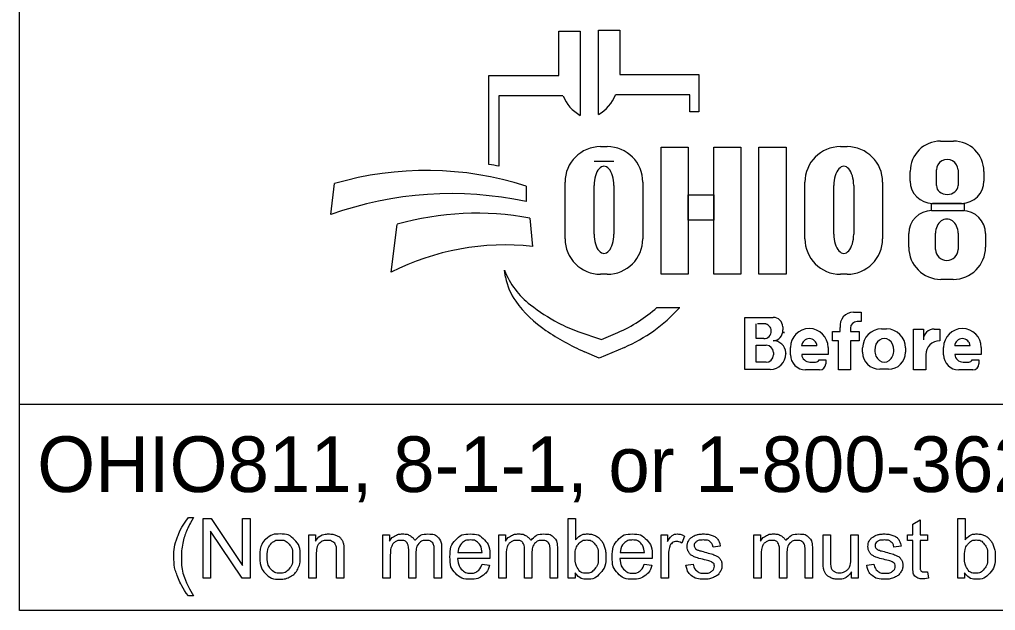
# Model space of a CAD drawing. Extents: x 0 to 34, y -32.5 to 22.
# Drawn here: x 2.378 to 4.831, y 2.305 to 3.791 of the extents above; entities that cross this region are included whole.
import ezdxf

# ---------------------------------------------------------------- set-up
doc = ezdxf.new("R2010")
doc.units = 0
doc.layers.add('GM_X_Adjacent_County', color=7, linetype='Continuous')
doc.layers.add('GM_X_Township', color=7, linetype='Continuous')

msp = doc.modelspace()

# ---------------------------------------------------------------- linework, layer by layer
at = {"layer": 'GM_X_Adjacent_County'}
for p, q in [((3.7335, 3.6502), (3.7335, 3.7617)), ((3.7335, 3.7617), (3.7872, 3.7617)), ((3.7872, 3.7617), (3.7872, 3.5496)), ((3.8329, 3.5519), (3.8329, 3.764)), ((3.8329, 3.764), (3.8865, 3.764)), ((3.8865, 3.764), (3.8865, 3.6525)), ((3.5576, 3.4263), (3.5576, 3.6502)), ((3.5576, 3.6502), (3.7335, 3.6502)), ((3.8865, 3.6525), (4.0857, 3.6525)), ((4.0857, 3.6525), (4.0857, 3.5587)), ((3.5828, 3.5987), (3.5828, 3.4219)), ((3.7439, 3.5987), (3.5828, 3.5987)), ((4.0625, 3.6011), (3.8761, 3.6011)), ((4.0625, 3.5587), (4.0625, 3.6011)), ((4.0857, 3.5587), (4.0625, 3.5587)), ((4.6931, 3.485), (4.7258, 3.485)), ((3.8385, 3.471), (3.8551, 3.471)), ((4.4416, 3.471), (4.4581, 3.471)), ((3.8718, 3.434), (3.822, 3.434)), ((4.683, 3.373), (4.683, 3.4123)), ((4.7371, 3.4123), (4.7371, 3.373)), ((4.6168, 3.3844), (4.6168, 3.4087)), ((4.8022, 3.4087), (4.8022, 3.3844)), ((3.1602, 3.3), (3.1696, 3.3781)), ((3.6509, 3.3716), (3.6509, 3.3328)), ((3.7491, 3.2395), (3.7491, 3.3815)), ((3.822, 3.2509), (3.822, 3.3732)), ((3.8718, 3.3732), (3.8718, 3.2509)), ((3.9445, 3.3815), (3.9445, 3.2395)), ((4.3521, 3.2395), (4.3521, 3.3815)), ((4.425, 3.2509), (4.425, 3.3732)), ((4.4748, 3.3732), (4.4748, 3.2509)), ((4.5476, 3.3815), (4.5476, 3.2395)), ((4.7462, 3.3284), (4.6728, 3.3284)), ((3.6608, 3.291), (3.6671, 3.2201)), ((4.671, 3.3101), (4.7483, 3.3101)), ((3.312, 3.1555), (3.3267, 3.2756)), ((4.6131, 3.2182), (4.6131, 3.2522)), ((4.6806, 3.2122), (4.6806, 3.2531)), ((4.7374, 3.2531), (4.7374, 3.2122)), ((4.8062, 3.2522), (4.8062, 3.2182)), ((3.5997, 3.1426), (3.5967, 3.1605)), ((3.8551, 3.15), (3.8385, 3.15)), ((4.4581, 3.15), (4.4416, 3.15)), ((4.7252, 3.1372), (4.6941, 3.1372)), ((3.98, 3.0667), (4.0375, 3.0667)), ((4.4739, 3.0544), (4.4934, 3.0544)), ((4.4934, 3.0544), (4.4934, 3.0315)), ((4.2013, 2.9109), (4.2013, 3.0417)), ((4.2013, 3.0417), (4.2725, 3.0417)), ((4.2293, 2.9882), (4.2293, 3.0251)), ((4.2545, 3.0251), (4.2332, 3.0251)), ((4.4934, 3.031), (4.4832, 3.031)), ((3.7816, 3.0063), (3.841, 2.9858)), ((3.841, 2.9858), (3.8821, 3.0036)), ((4.2963, 3.0179), (4.2963, 3.01)), ((4.4213, 2.9831), (4.4213, 3.0061)), ((4.4213, 3.0061), (4.4406, 3.0061)), ((4.4406, 3.0061), (4.4406, 3.0165)), ((4.4667, 3.0145), (4.4667, 3.0061)), ((4.4667, 3.0061), (4.4883, 3.0061)), ((4.4883, 3.0061), (4.4883, 2.9831)), ((4.5451, 3.0126), (4.5573, 3.0126)), ((4.6254, 2.9097), (4.6254, 3.0124)), ((4.6254, 3.0124), (4.6499, 3.0124)), ((4.6499, 3.0124), (4.6499, 2.9855)), ((4.6772, 3.0124), (4.691, 3.0124)), ((4.691, 3.0124), (4.691, 2.9828)), ((4.2487, 2.9882), (4.2293, 2.9882)), ((4.2293, 2.9288), (4.2293, 2.9716)), ((4.2293, 2.9716), (4.2548, 2.9716)), ((4.3824, 2.9701), (4.3439, 2.9701)), ((4.4362, 2.9831), (4.4213, 2.9831)), ((4.4362, 2.9097), (4.4362, 2.9831)), ((4.4883, 2.9831), (4.4667, 2.9831)), ((4.4667, 2.9831), (4.4667, 2.9097)), ((4.7674, 2.9701), (4.7288, 2.9701)), ((3.835, 2.9388), (3.7976, 2.9552)), ((3.8983, 2.9663), (3.835, 2.9388)), ((4.2729, 2.9535), (4.2729, 2.9471)), ((4.3043, 2.9506), (4.3043, 2.9503)), ((4.3159, 2.9477), (4.3159, 2.9661)), ((4.4104, 2.9485), (4.344, 2.9485)), ((4.4104, 2.9661), (4.4104, 2.9485)), ((4.4973, 2.954), (4.4973, 2.9648)), ((4.6051, 2.9648), (4.6051, 2.954)), ((4.6559, 2.9479), (4.6559, 2.9097)), ((4.7008, 2.9477), (4.7008, 2.9661)), ((4.7953, 2.9485), (4.7289, 2.9485)), ((4.7953, 2.9661), (4.7953, 2.9485)), ((4.2546, 2.9288), (4.2293, 2.9288)), ((4.3649, 2.9292), (4.379, 2.9292)), ((4.3876, 2.9348), (4.4045, 2.9348)), ((4.4045, 2.9348), (4.4045, 2.925)), ((4.7498, 2.9292), (4.7639, 2.9292)), ((4.7725, 2.9348), (4.7894, 2.9348)), ((4.7894, 2.9348), (4.7894, 2.925)), ((4.265, 2.9109), (4.2013, 2.9109)), ((4.3892, 2.9097), (4.3538, 2.9097)), ((4.4667, 2.9097), (4.4362, 2.9097)), ((4.5623, 2.9113), (4.5401, 2.9113)), ((4.6559, 2.9097), (4.6254, 2.9097)), ((4.7742, 2.9097), (4.7388, 2.9097))]:
    msp.add_line(p, q, dxfattribs=at)
for points in [[(3.991, 3.47), (4.0589, 3.47), (4.0589, 3.15), (3.991, 3.15)], [(4.1231, 3.47), (4.1911, 3.47), (4.1911, 3.15), (4.1231, 3.15)], [(4.2364, 3.47), (4.3052, 3.47), (4.3052, 3.15), (4.2364, 3.15)], [(4.0589, 3.3501), (4.1231, 3.3501), (4.1231, 3.2861), (4.0589, 3.2861)], [(4.6706, 3.3284), (4.7523, 3.3284), (4.7523, 3.3099), (4.6706, 3.3099)]]:
    msp.add_lwpolyline(points, close=True, dxfattribs=at)
for points in [[(2.8021, 2.5385), (2.8153, 2.5385)], [(2.8389, 2.3858), (2.8389, 2.536), (2.8592, 2.536), (2.9382, 2.418), (2.9382, 2.536), (2.9572, 2.536), (2.9572, 2.3858), (2.9369, 2.3858), (2.8579, 2.5037), (2.8579, 2.3858), (2.8389, 2.3858)], [(3.7743, 2.3858), (3.7573, 2.3858), (3.7573, 2.536), (3.7757, 2.536), (3.7757, 2.4824)], [(4.6233, 2.4177), (4.6233, 2.4803), (4.6097, 2.4803), (4.6097, 2.4946), (4.6233, 2.4946), (4.6233, 2.5216), (4.6417, 2.5326), (4.6417, 2.4946), (4.6601, 2.4946), (4.6601, 2.4803), (4.6417, 2.4803), (4.6417, 2.4166)], [(4.7534, 2.3858), (4.7363, 2.3858), (4.7363, 2.536), (4.7548, 2.536), (4.7548, 2.4824)], [(3.1048, 2.3858), (3.1048, 2.4946), (3.1214, 2.4946), (3.1214, 2.4792)], [(3.2912, 2.3858), (3.2912, 2.4946), (3.3077, 2.4946), (3.3077, 2.4793)], [(3.5826, 2.3858), (3.5826, 2.4946), (3.5991, 2.4946), (3.5991, 2.4793)], [(3.9904, 2.3858), (3.9904, 2.4946), (4.007, 2.4946), (4.007, 2.4782)], [(4.0495, 2.4912), (4.043, 2.4741)], [(4.2236, 2.3858), (4.2236, 2.4946), (4.2401, 2.4946), (4.2401, 2.4793)], [(4.3979, 2.4272), (4.3979, 2.4946), (4.4164, 2.4946), (4.4164, 2.4343)], [(4.4676, 2.4364), (4.4676, 2.4946), (4.4861, 2.4946), (4.4861, 2.3858), (4.4696, 2.3858)], [(3.3743, 2.449), (3.3743, 2.3858), (3.3559, 2.3858), (3.3559, 2.4565)], [(3.4388, 2.4605), (3.4388, 2.3858), (3.4203, 2.3858), (3.4203, 2.4543)], [(3.6657, 2.449), (3.6657, 2.3858), (3.6473, 2.3858), (3.6473, 2.4565)], [(3.7301, 2.4605), (3.7301, 2.3858), (3.7117, 2.3858), (3.7117, 2.4543)], [(4.1394, 2.4665), (4.1213, 2.4641)], [(4.3067, 2.449), (4.3067, 2.3858), (4.2883, 2.3858), (4.2883, 2.4565)], [(4.3711, 2.4605), (4.3711, 2.3858), (4.3527, 2.3858), (4.3527, 2.4543)], [(4.594, 2.4665), (4.5759, 2.4641)], [(3.1233, 2.4452), (3.1233, 2.3858), (3.1048, 2.3858)], [(3.1932, 2.4527), (3.1932, 2.3858), (3.1748, 2.3858), (3.1748, 2.4519)], [(3.3097, 2.4422), (3.3097, 2.3858), (3.2912, 2.3858)], [(3.56, 2.4355), (3.4788, 2.4355)], [(3.4799, 2.4506), (3.5406, 2.4506)], [(3.601, 2.4422), (3.601, 2.3858), (3.5826, 2.3858)], [(3.968, 2.4355), (3.8868, 2.4355)], [(3.8879, 2.4506), (3.9486, 2.4506)], [(4.0088, 2.4428), (4.0088, 2.3858), (3.9904, 2.3858)], [(4.242, 2.4422), (4.242, 2.3858), (4.2236, 2.3858)], [(3.5404, 2.4209), (3.5595, 2.4185)], [(3.9484, 2.4209), (3.9675, 2.4185)], [(4.053, 2.4183), (4.0712, 2.4212)], [(4.5076, 2.4183), (4.5258, 2.4212)], [(3.7743, 2.3994), (3.7743, 2.3858)], [(4.4696, 2.3858), (4.4696, 2.4019)], [(4.6601, 2.4022), (4.6628, 2.386)], [(4.7534, 2.3994), (4.7534, 2.3858)], [(2.8153, 2.3416), (2.8021, 2.3416)]]:
    msp.add_lwpolyline(points, dxfattribs=at)
for centre, radius, start, end in [((3.8353, 3.6355), 0.0985, 201.9296, 240.7469), ((3.7847, 3.6378), 0.0985, 299.2531, 338.0704), ((4.6931, 3.4087), 0.0763, 90, 180), ((4.7258, 3.4087), 0.0763, 0, 90), ((3.8385, 3.3815), 0.0895, 90, 180), ((3.8551, 3.3815), 0.0895, 0, 90), ((4.4416, 3.3815), 0.0895, 90, 180), ((4.4581, 3.3815), 0.0895, 0, 90), ((3.3997, 2.592), 0.8191, 72.1402, 106.3144), ((3.4295, 2.6173), 0.8191, 79.2074, 81.0007), ((4.6728, 3.3844), 0.056, 180, 270), ((4.7462, 3.3844), 0.056, 270, 0), ((3.4628, 2.4609), 0.8919, 77.8238, 109.8274), ((3.5267, 2.5713), 0.7322, 79.44, 105.8467), ((4.671, 3.2522), 0.0579, 90, 180), ((4.7483, 3.2522), 0.0579, 0, 90), ((3.8385, 3.2395), 0.0895, 180, 270), ((3.8551, 3.2395), 0.0895, 270, 0), ((4.4416, 3.2395), 0.0895, 180, 270), ((4.4581, 3.2395), 0.0895, 270, 0), ((3.5987, 2.588), 0.6357, 83.8248, 116.8021), ((4.6941, 3.2182), 0.081, 180, 270), ((4.7252, 3.2182), 0.081, 270, 0), ((3.7841, 3.2326), 0.2008, 201.0457, 232.5314), ((3.741, 3.1667), 0.1433, 189.6817, 216.0884), ((3.8747, 3.2641), 0.3088, 216.0884, 235.7167), ((3.9766, 3.4838), 0.5173, 232.5314, 241.794), ((3.7387, 3.3341), 0.3602, 293.4582, 312.0712), ((3.7387, 3.3341), 0.401, 293.4582, 317.8286), ((4.4739, 3.0209), 0.0335, 90, 187.5187), ((3.8914, 3.325), 0.3371, 241.794, 250.9821), ((4.2505, 3.0082), 0.0169, 357.8325, 90), ((4.2725, 3.0179), 0.0238, 0, 90), ((4.4832, 3.0145), 0.0165, 90, 180), ((4.0412, 3.5084), 0.6044, 235.7167, 246.2325), ((4.2487, 3.0069), 0.0187, 270, 2.0582), ((4.2721, 3.0072), 0.0243, 270, 6.6529), ((4.2827, 3.0057), 0.0175, 347.4023, 0), ((4.3631, 2.9661), 0.0473, 0, 180), ((4.5451, 2.9648), 0.0478, 90, 180), ((4.5573, 2.9648), 0.0478, 0, 90), ((4.6768, 2.9855), 0.0269, 89.2449, 180), ((4.7481, 2.9661), 0.0473, 0, 180), ((4.2548, 2.9535), 0.0181, 0, 90), ((4.2722, 2.9508), 0.0321, 4.0748, 90), ((4.3632, 2.9691), 0.0193, 2.9632, 177.0368), ((4.6908, 2.9479), 0.0349, 89.6033, 180), ((4.7481, 2.9691), 0.0193, 2.9632, 177.0368), ((4.2546, 2.9471), 0.0184, 270, 0), ((4.265, 2.9503), 0.0393, 270, 0), ((4.2714, 2.9506), 0.033, 0, 11.7502), ((4.3538, 2.9477), 0.038, 180, 270), ((4.3649, 2.9502), 0.021, 184.827, 270), ((4.5401, 2.954), 0.0428, 180, 270), ((4.5623, 2.954), 0.0428, 270, 0), ((4.7388, 2.9477), 0.038, 180, 270), ((4.7498, 2.9502), 0.021, 184.827, 270), ((4.379, 2.9386), 0.00938, 270, 335.9979), ((4.3892, 2.925), 0.0152, 270, 0), ((4.7639, 2.9386), 0.00938, 270, 335.9979), ((4.7742, 2.925), 0.0152, 270, 0)]:
    msp.add_arc(centre, radius, start, end, dxfattribs=at)
for centre, major_axis, ratio, start_param, end_param in [((4.71, 3.4123), (0.0271, 0), 0.969373, 0, 3.141593), ((3.8469, 3.3732), (0, 0.0484), 0.514403, 4.712389, 7.853982), ((4.4499, 3.3732), (0, 0.0484), 0.514403, 4.712389, 7.853982), ((4.71, 3.373), (0.0271, 0), 0.818453, 3.141593, 6.283185), ((4.709, 3.2531), (0, 0.0358), 0.794529, 4.712389, 7.853982), ((3.8469, 3.2509), (0, 0.0484), 0.514403, 1.570796, 4.712389), ((4.4499, 3.2509), (0, 0.0484), 0.514403, 1.570796, 4.712389), ((4.709, 3.2122), (0.0284, 0), 0.959837, 3.141593, 6.283185), ((4.5517, 2.9594), (0, 0.029), 0.832186, 4.712389, 7.853982), ((4.5517, 2.9594), (0, 0.0302), 0.797287, 1.570796, 4.712389)]:
    msp.add_ellipse(centre, major_axis=major_axis, ratio=ratio, start_param=start_param, end_param=end_param, dxfattribs=at)
for points in [[(2.8021, 2.3416), (2.7869, 2.3609), (2.7763, 2.3867), (2.7657, 2.4125), (2.7657, 2.4402), (2.7657, 2.4645), (2.7736, 2.4869), (2.7829, 2.5128), (2.8021, 2.5385)], [(2.8153, 2.5385), (2.8029, 2.5172), (2.7989, 2.5081), (2.7927, 2.4939), (2.7891, 2.4786), (2.7847, 2.4594), (2.7847, 2.4401), (2.7847, 2.3908), (2.8153, 2.3416)], [(2.9814, 2.4402), (2.9814, 2.4704), (2.9981, 2.485), (3.0122, 2.497), (3.0323, 2.497), (3.0547, 2.497), (3.069, 2.4824), (3.0832, 2.4677), (3.0832, 2.4418), (3.0832, 2.4208), (3.0769, 2.4087), (3.0706, 2.3967), (3.0586, 2.3901), (3.0466, 2.3834), (3.0323, 2.3834), (3.0095, 2.3834), (2.9954, 2.398), (2.9814, 2.4127), (2.9814, 2.4402)], [(3.0003, 2.4402), (3.0003, 2.4193), (3.0094, 2.4089), (3.0185, 2.3985), (3.0323, 2.3985), (3.046, 2.3985), (3.0551, 2.409), (3.0642, 2.4194), (3.0642, 2.4408), (3.0642, 2.461), (3.0551, 2.4714), (3.0459, 2.4818), (3.0323, 2.4818), (3.0185, 2.4818), (3.0094, 2.4715), (3.0003, 2.4611), (3.0003, 2.4402)], [(3.1214, 2.4792), (3.1334, 2.497), (3.156, 2.497), (3.1659, 2.497), (3.1741, 2.4935), (3.1823, 2.49), (3.1864, 2.4842), (3.1905, 2.4785), (3.1922, 2.4706), (3.1932, 2.4655), (3.1932, 2.4527)], [(3.1748, 2.4519), (3.1748, 2.4632), (3.1726, 2.4688), (3.1705, 2.4744), (3.165, 2.4777), (3.1595, 2.481), (3.1521, 2.481), (3.1404, 2.481), (3.1318, 2.4736), (3.1233, 2.4661), (3.1233, 2.4452)], [(3.3077, 2.4793), (3.3128, 2.4873), (3.3214, 2.4922), (3.3299, 2.497), (3.3407, 2.497), (3.3528, 2.497), (3.3606, 2.492), (3.3683, 2.487), (3.3715, 2.478), (3.3844, 2.497), (3.4051, 2.497), (3.4213, 2.497), (3.43, 2.4881), (3.4388, 2.4791), (3.4388, 2.4605)], [(3.3559, 2.4565), (3.3559, 2.4687), (3.3514, 2.4749), (3.3469, 2.481), (3.3366, 2.481), (3.3288, 2.481), (3.3222, 2.4769), (3.3156, 2.4728), (3.3126, 2.465), (3.3097, 2.4571), (3.3097, 2.4422)], [(3.4203, 2.4543), (3.4203, 2.4654), (3.4185, 2.4702), (3.4168, 2.4751), (3.412, 2.4781), (3.4073, 2.481), (3.401, 2.481), (3.3895, 2.481), (3.3819, 2.4734), (3.3743, 2.4658), (3.3743, 2.449)], [(3.5595, 2.4185), (3.555, 2.4018), (3.5428, 2.3926), (3.5306, 2.3834), (3.5117, 2.3834), (3.4878, 2.3834), (3.4738, 2.3981), (3.4598, 2.4128), (3.4598, 2.4393), (3.4598, 2.4667), (3.474, 2.4819), (3.4881, 2.497), (3.5106, 2.497), (3.5324, 2.497), (3.5463, 2.4822), (3.5601, 2.4673), (3.5601, 2.4404), (3.5601, 2.4388), (3.56, 2.4355)], [(3.5406, 2.4506), (3.5394, 2.4644), (3.5337, 2.4712), (3.5249, 2.4819), (3.5108, 2.4819), (3.4981, 2.4819), (3.4894, 2.4734), (3.4808, 2.4649), (3.4799, 2.4506)], [(3.5991, 2.4793), (3.6042, 2.4873), (3.6127, 2.4922), (3.6212, 2.497), (3.6321, 2.497), (3.6442, 2.497), (3.6519, 2.492), (3.6597, 2.487), (3.6628, 2.478), (3.6758, 2.497), (3.6965, 2.497), (3.7127, 2.497), (3.7214, 2.4881), (3.7301, 2.4791), (3.7301, 2.4605)], [(3.6473, 2.4565), (3.6473, 2.4687), (3.6428, 2.4749), (3.6383, 2.481), (3.628, 2.481), (3.6202, 2.481), (3.6136, 2.4769), (3.607, 2.4728), (3.604, 2.465), (3.601, 2.4571), (3.601, 2.4422)], [(3.7117, 2.4543), (3.7117, 2.4654), (3.7099, 2.4702), (3.7081, 2.4751), (3.7034, 2.4781), (3.6987, 2.481), (3.6923, 2.481), (3.6809, 2.481), (3.6733, 2.4734), (3.6657, 2.4658), (3.6657, 2.449)], [(3.7741, 2.441), (3.7741, 2.4215), (3.7794, 2.4128), (3.7881, 2.3985), (3.8029, 2.3985), (3.815, 2.3985), (3.8238, 2.409), (3.8326, 2.4195), (3.8326, 2.4403), (3.8326, 2.4616), (3.8241, 2.4718), (3.8157, 2.4819), (3.8038, 2.4819), (3.7917, 2.4819), (3.7829, 2.4714), (3.7741, 2.4609), (3.7741, 2.441)], [(3.7757, 2.4824), (3.7874, 2.497), (3.8055, 2.497), (3.8155, 2.497), (3.8245, 2.493), (3.8335, 2.489), (3.8392, 2.4816), (3.845, 2.4743), (3.8483, 2.464), (3.8516, 2.4536), (3.8516, 2.4419), (3.8516, 2.4139), (3.8378, 2.3987), (3.8239, 2.3834), (3.8046, 2.3834), (3.7853, 2.3834), (3.7743, 2.3994)], [(3.9675, 2.4185), (3.963, 2.4018), (3.9508, 2.3926), (3.9386, 2.3834), (3.9196, 2.3834), (3.8958, 2.3834), (3.8818, 2.3981), (3.8678, 2.4128), (3.8678, 2.4393), (3.8678, 2.4667), (3.882, 2.4819), (3.8961, 2.497), (3.9186, 2.497), (3.9404, 2.497), (3.9543, 2.4822), (3.9681, 2.4673), (3.9681, 2.4404), (3.9681, 2.4388), (3.968, 2.4355)], [(3.9486, 2.4506), (3.9474, 2.4644), (3.9417, 2.4712), (3.9328, 2.4819), (3.9188, 2.4819), (3.9061, 2.4819), (3.8974, 2.4734), (3.8888, 2.4649), (3.8879, 2.4506)], [(4.007, 2.4782), (4.0133, 2.4897), (4.0187, 2.4934), (4.0241, 2.497), (4.0305, 2.497), (4.0398, 2.497), (4.0495, 2.4912)], [(4.1213, 2.4641), (4.1201, 2.4725), (4.1142, 2.4772), (4.1083, 2.4819), (4.0975, 2.4819), (4.0848, 2.4819), (4.0794, 2.4777), (4.0739, 2.4735), (4.0739, 2.4679), (4.0739, 2.4643), (4.0762, 2.4614), (4.0785, 2.4584), (4.0833, 2.4565), (4.086, 2.4555), (4.0996, 2.4518), (4.1192, 2.4466), (4.1269, 2.4432), (4.1347, 2.4399), (4.1391, 2.4336), (4.1435, 2.4272), (4.1435, 2.4178), (4.1435, 2.4086), (4.1381, 2.4004), (4.1327, 2.3923), (4.1226, 2.3879), (4.1124, 2.3834), (4.0996, 2.3834), (4.0784, 2.3834), (4.0672, 2.3922), (4.0561, 2.401), (4.053, 2.4183)], [(4.0712, 2.4212), (4.0727, 2.4102), (4.0798, 2.4044), (4.0868, 2.3985), (4.0995, 2.3985), (4.1122, 2.3985), (4.1184, 2.4037), (4.1245, 2.4089), (4.1245, 2.4158), (4.1245, 2.4221), (4.1191, 2.4257), (4.1153, 2.4282), (4.1002, 2.432), (4.0799, 2.4371), (4.072, 2.4408), (4.0642, 2.4445), (4.0601, 2.4511), (4.0561, 2.4577), (4.0561, 2.4657), (4.0561, 2.473), (4.0594, 2.4792), (4.0628, 2.4854), (4.0685, 2.4895), (4.0728, 2.4926), (4.0803, 2.4948), (4.0877, 2.497), (4.0962, 2.497), (4.109, 2.497), (4.1187, 2.4934), (4.1284, 2.4897), (4.133, 2.4834), (4.1377, 2.4771), (4.1394, 2.4665)], [(4.2401, 2.4793), (4.2452, 2.4873), (4.2537, 2.4922), (4.2622, 2.497), (4.2731, 2.497), (4.2852, 2.497), (4.2929, 2.492), (4.3007, 2.487), (4.3038, 2.478), (4.3168, 2.497), (4.3375, 2.497), (4.3537, 2.497), (4.3624, 2.4881), (4.3711, 2.4791), (4.3711, 2.4605)], [(4.2883, 2.4565), (4.2883, 2.4687), (4.2838, 2.4749), (4.2793, 2.481), (4.269, 2.481), (4.2612, 2.481), (4.2546, 2.4769), (4.248, 2.4728), (4.245, 2.465), (4.242, 2.4571), (4.242, 2.4422)], [(4.3527, 2.4543), (4.3527, 2.4654), (4.3509, 2.4702), (4.3491, 2.4751), (4.3444, 2.4781), (4.3397, 2.481), (4.3333, 2.481), (4.3219, 2.481), (4.3143, 2.4734), (4.3067, 2.4658), (4.3067, 2.449)], [(4.5759, 2.4641), (4.5747, 2.4725), (4.5688, 2.4772), (4.5629, 2.4819), (4.5521, 2.4819), (4.5394, 2.4819), (4.5339, 2.4777), (4.5285, 2.4735), (4.5285, 2.4679), (4.5285, 2.4643), (4.5308, 2.4614), (4.533, 2.4584), (4.5378, 2.4565), (4.5406, 2.4555), (4.5542, 2.4518), (4.5737, 2.4466), (4.5815, 2.4432), (4.5893, 2.4399), (4.5937, 2.4336), (4.5981, 2.4272), (4.5981, 2.4178), (4.5981, 2.4086), (4.5927, 2.4004), (4.5873, 2.3923), (4.5772, 2.3879), (4.567, 2.3834), (4.5542, 2.3834), (4.5329, 2.3834), (4.5218, 2.3922), (4.5107, 2.401), (4.5076, 2.4183)], [(4.5258, 2.4212), (4.5273, 2.4102), (4.5343, 2.4044), (4.5414, 2.3985), (4.554, 2.3985), (4.5668, 2.3985), (4.5729, 2.4037), (4.5791, 2.4089), (4.5791, 2.4158), (4.5791, 2.4221), (4.5736, 2.4257), (4.5698, 2.4282), (4.5548, 2.432), (4.5345, 2.4371), (4.5266, 2.4408), (4.5188, 2.4445), (4.5147, 2.4511), (4.5107, 2.4577), (4.5107, 2.4657), (4.5107, 2.473), (4.514, 2.4792), (4.5173, 2.4854), (4.5231, 2.4895), (4.5274, 2.4926), (4.5348, 2.4948), (4.5423, 2.497), (4.5508, 2.497), (4.5636, 2.497), (4.5733, 2.4934), (4.583, 2.4897), (4.5876, 2.4834), (4.5922, 2.4771), (4.594, 2.4665)], [(4.7532, 2.441), (4.7532, 2.4215), (4.7585, 2.4128), (4.7672, 2.3985), (4.782, 2.3985), (4.7941, 2.3985), (4.8029, 2.409), (4.8116, 2.4195), (4.8116, 2.4403), (4.8116, 2.4616), (4.8032, 2.4718), (4.7948, 2.4819), (4.7828, 2.4819), (4.7708, 2.4819), (4.762, 2.4714), (4.7532, 2.4609), (4.7532, 2.441)], [(4.7548, 2.4824), (4.7664, 2.497), (4.7846, 2.497), (4.7946, 2.497), (4.8036, 2.493), (4.8125, 2.489), (4.8183, 2.4816), (4.8241, 2.4743), (4.8274, 2.464), (4.8306, 2.4536), (4.8306, 2.4419), (4.8306, 2.4139), (4.8168, 2.3987), (4.803, 2.3834), (4.7836, 2.3834), (4.7644, 2.3834), (4.7534, 2.3994)], [(4.043, 2.4741), (4.0363, 2.478), (4.0295, 2.478), (4.0235, 2.478), (4.0187, 2.4744), (4.0139, 2.4708), (4.0119, 2.4643), (4.0088, 2.4545), (4.0088, 2.4428)], [(3.4788, 2.4355), (3.4799, 2.4176), (3.489, 2.408), (3.4981, 2.3985), (3.5117, 2.3985), (3.5219, 2.3985), (3.5291, 2.4039), (3.5362, 2.4092), (3.5404, 2.4209)], [(3.8868, 2.4355), (3.8879, 2.4176), (3.897, 2.408), (3.9061, 2.3985), (3.9197, 2.3985), (3.9299, 2.3985), (3.937, 2.4039), (3.9442, 2.4092), (3.9484, 2.4209)], [(4.4164, 2.4343), (4.4164, 2.4199), (4.4175, 2.4149), (4.4192, 2.4076), (4.4249, 2.4035), (4.4305, 2.3993), (4.4388, 2.3993), (4.4471, 2.3993), (4.4543, 2.4036), (4.4616, 2.4078), (4.4646, 2.4151), (4.4676, 2.4225), (4.4676, 2.4364)], [(4.4696, 2.4019), (4.4569, 2.3834), (4.4351, 2.3834), (4.4255, 2.3834), (4.4171, 2.3871), (4.4088, 2.3908), (4.4047, 2.3964), (4.4007, 2.4019), (4.3991, 2.41), (4.3979, 2.4155), (4.3979, 2.4272)], [(4.6628, 2.386), (4.655, 2.3843), (4.6488, 2.3843), (4.6388, 2.3843), (4.6333, 2.3875), (4.6278, 2.3907), (4.6255, 2.3959), (4.6233, 2.401), (4.6233, 2.4177)], [(4.6417, 2.4166), (4.6417, 2.4087), (4.6427, 2.4064), (4.6436, 2.4042), (4.6458, 2.4028), (4.648, 2.4015), (4.6521, 2.4015), (4.6551, 2.4015), (4.6601, 2.4022)]]:
    msp.add_open_spline(points, degree=3, dxfattribs=at)
at = {"layer": 'GM_X_Township'}
for p, q in [((2.3775, 2.3047), (2.3775, 4.6422)), ((6.6275, 2.8225), (2.3775, 2.8225)), ((6.6275, 2.3047), (2.3775, 2.3047))]:
    msp.add_line(p, q, dxfattribs=at)

# ---------------------------------------------------------------- texts
at = {"layer": 'GM_X_Adjacent_County'}
msp.add_text('OHIO811, 8-1-1, or 1-800-362-2764', height=0.14, dxfattribs=at).set_placement((2.422, 2.6025))

doc.saveas('drawing.dxf')
